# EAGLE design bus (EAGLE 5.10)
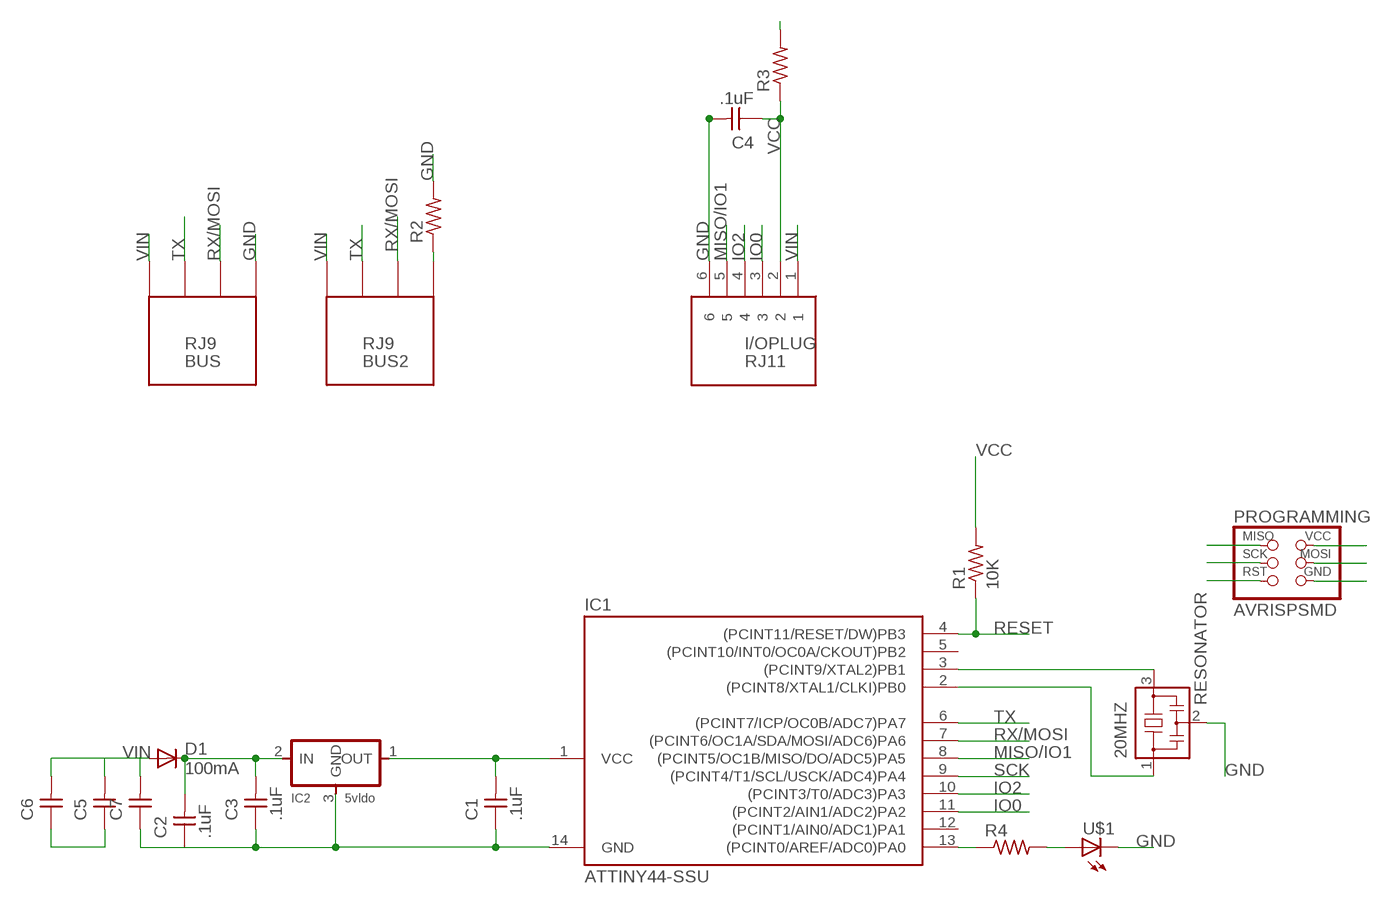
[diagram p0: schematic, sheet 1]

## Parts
20MHZ  RESONATOR  [EFOBM]
BUS  RJ9  [RJ9_SMD]
BUS2  RJ9  [RJ9_SMD]
C1  .1uF  UNPOLARIZED_CAPACITOR1206  [1206]
C2  .1uF  UNPOLARIZED_CAPACITOR1206  [1206]
C3  .1uF  UNPOLARIZED_CAPACITOR1206  [1206]
C4  .1uF  UNPOLARIZED_CAPACITOR1206  [1206]
C5  UNPOLARIZED_CAPACITOR1206  [1206]
C6  UNPOLARIZED_CAPACITOR1206  [1206]
C7  UNPOLARIZED_CAPACITOR1206  [1206]
D1  100mA  DIODESOD123  [SOD123]
I/OPLUG  RJ11  [RJ11_SMD]
IC1  ATTINY44-SSU  [SOIC14]
IC2  5vldo  REGULATORSOT23  [SOT23]
PROGRAMMING  AVRISPSMD  [2X03SMD]
R1  10K  RESISTOR1206  [1206]
R2  RESISTOR1206  [1206]
R3  RESISTOR1206  [1206]
R4  RESISTOR1206  [1206]
U$1  LED1206  [1206]

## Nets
GND: 20MHZ.2 BUS.4 C1.1 C2.1 C3.1 C4.2 C7.1 I/OPLUG.6 IC1.14(GND) IC2.3(GND) PROGRAMMING.6(GND) R2.2 U$1.2(C)
GND1: BUS2.4 C5.1 C6.1 R2.1
IO0: I/OPLUG.3 IC1.11((PCINT2/AIN1/ADC2)PA2)
IO2: I/OPLUG.4 IC1.10((PCINT3/T0/ADC3)PA3)
MISO/IO1: I/OPLUG.5 IC1.8((PCINT5/OC1B/MISO/DO/ADC5)PA5) PROGRAMMING.1(MISO)
N$1: 20MHZ.3 IC1.3((PCINT9/XTAL2)PB1)
N$2: 20MHZ.1 IC1.2((PCINT8/XTAL1/CLKI)PB0)
N$4: C4.1 I/OPLUG.2 R3.1
N$5: IC1.13((PCINT0/AREF/ADC0)PA0) R4.1
N$6: C2.2 C3.2 D1.CATHODE(C) IC2.2(IN)
N$7: R4.2 U$1.1(A)
RESET: IC1.4((PCINT11/RESET/DW)PB3) PROGRAMMING.5(RST) R1.1
RX/MOSI: BUS2.3 BUS.3 IC1.7((PCINT6/OC1A/SDA/MOSI/ADC6)PA6) PROGRAMMING.4(MOSI)
SCK: IC1.9((PCINT4/T1/SCL/USCK/ADC4)PA4) PROGRAMMING.3(SCK)
TX: BUS2.2 BUS.2 IC1.6((PCINT7/ICP/OC0B/ADC7)PA7)
VCC: C1.2 IC1.1(VCC) IC2.1(OUT) PROGRAMMING.2(VCC) R1.2 R3.2
VIN: BUS2.1 BUS.1 C5.2 C6.2 C7.2 D1.ANODE(A) I/OPLUG.1
Unconnected: IC1.5((PCINT10/INT0/OC0A/CKOUT)PB2) IC1.12((PCINT1/AIN0/ADC1)PA1)

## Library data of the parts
20MHZ = fab:RESONATOR
BUS BUS2 = nadya:RJ9
C1-C7 = ng:UNPOLARIZED_CAPACITOR: unpolarized_capacitor
D1 = ng:DIODE: DIODE
I/OPLUG = nadya:RJ11
IC1 = fab:ATTINY44
IC2 = fab:REGULATOR
PROGRAMMING = fab:AVRISP
R1-R4 = ng:RESISTOR
U$1 = ng:LED

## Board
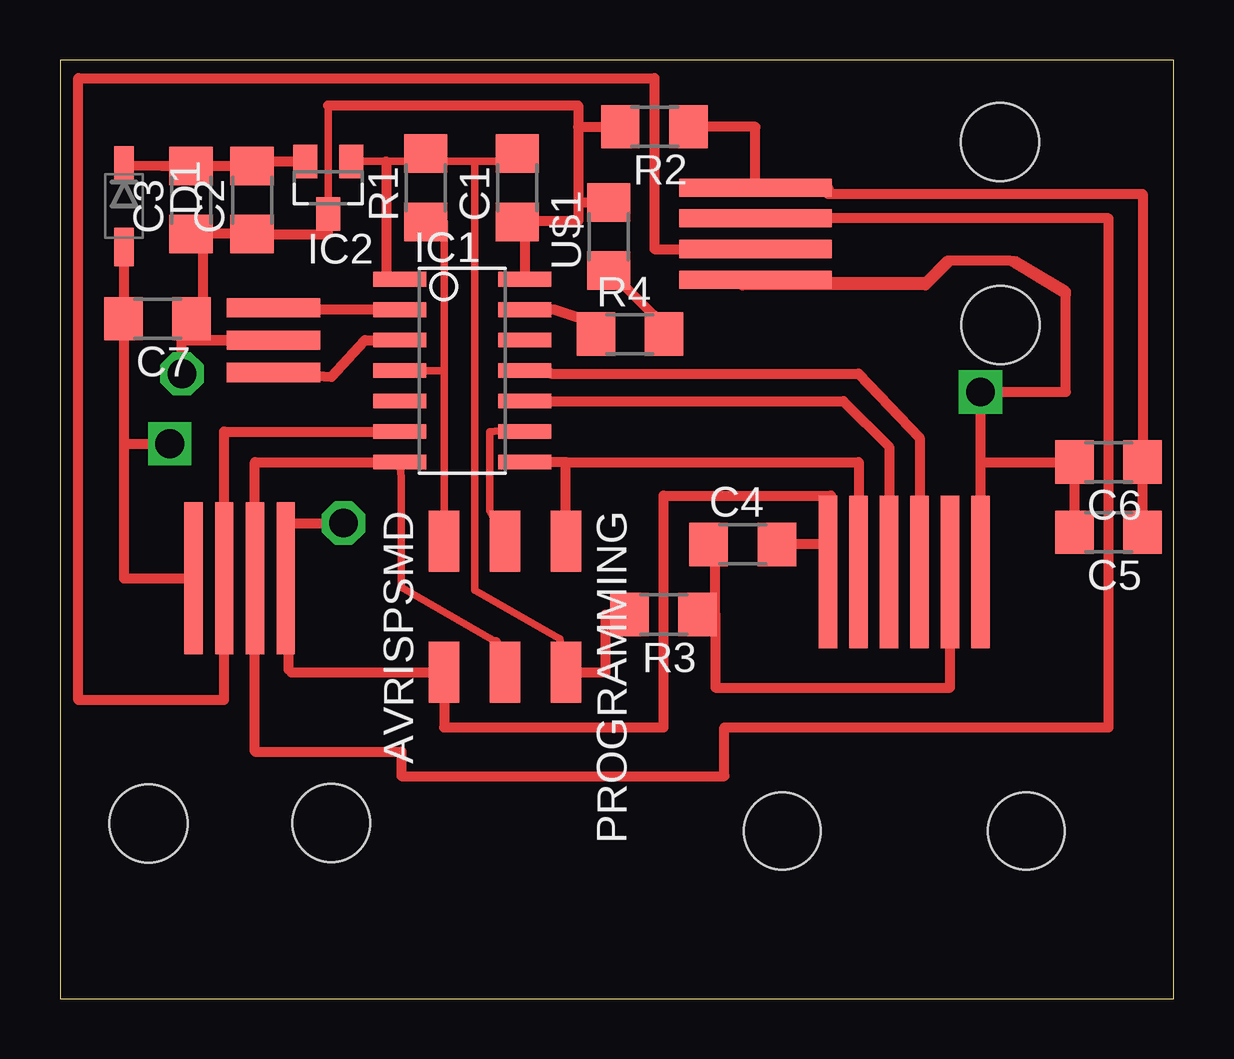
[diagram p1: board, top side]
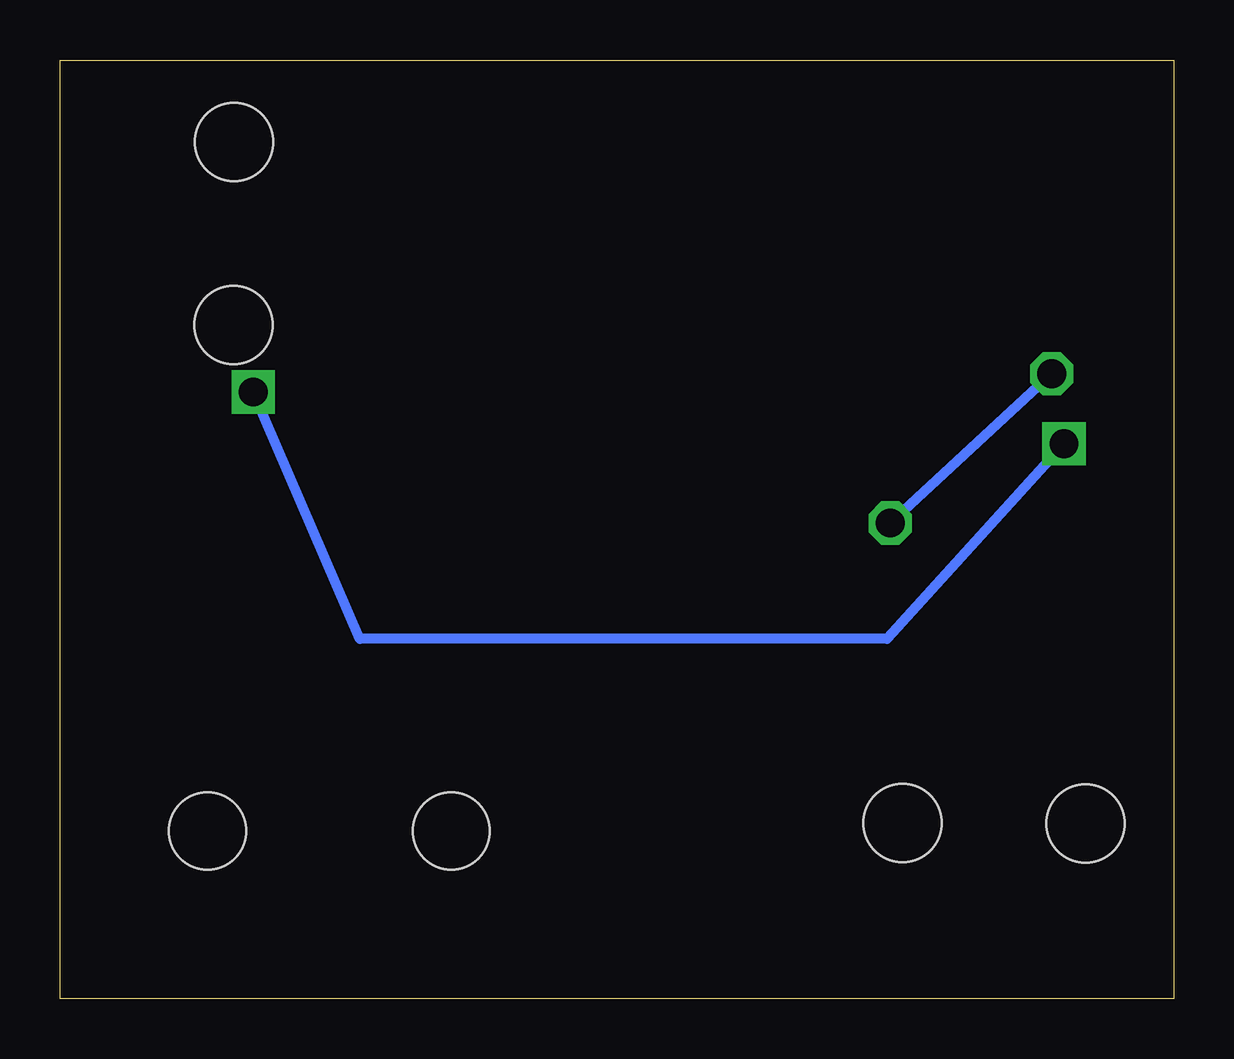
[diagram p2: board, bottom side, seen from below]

Size 46.41 x 39.11 mm. Coordinates in mm from the lower left corner, seen from the top.
Outline: 0,0 46.41,0 46.41,39.11 0,39.11 0,0
Copper layers (1*16): Top 0.035mm / dielectric 1.5mm / Bottom 0.035mm
Design rules "default": minimum track width 10mil, minimum drill 24mil, track to track 8mil, track to pad 8mil, pad to pad 8mil, via to via 8mil, smd to smd 8mil, copper to edge 40mil, drill to drill 8mil, minimum pad ring 10mil, minimum via ring 8mil, stop-mask expansion 4mil, vias tented up to drill 0mil, thermal gap 10mil

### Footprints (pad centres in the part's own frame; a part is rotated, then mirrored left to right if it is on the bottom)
EFOBM = smd 0.8 x 3.9: 1 -1.35,0; 2 0,0; 3 1.35,0
RJ9_SMD = smd 0.76 x 6.35: 1 -1.93,3.16; 2 -0.65,3.16; 3 0.63,3.16; 4 1.91,3.16 | hole 3.25: -3.81,-7.05; 3.81,-7.03
1206 = smd 1.6 x 1.803: 1 -1.422,0; 2 1.422,0
SOD123 = smd 1.6 x 0.8: ANODE 1.7,0; CATHODE -1.7,0
RJ11_SMD = smd 0.762 x 6.35: 1 3.175,-3.175; 2 1.905,-3.175; 3 0.635,-3.175; 4 -0.635,-3.175; 5 -1.905,-3.175; 6 -3.175,-3.175 | hole 3.2: -5.08,-13.97; 5.08,-13.97
SOIC14 = smd 0.61 x 2.21: 1 -3.81,-2.603; 2 -2.54,-2.603; 3 -1.27,-2.603; 4 0,-2.603; 5 1.27,-2.603; 6 2.54,-2.603; 7 3.81,-2.603; 8 3.81,2.603; 9 2.54,2.603; 10 1.27,2.603; 11 0,2.603; 12 -1.27,2.603; 13 -2.54,2.603; 14 -3.81,2.603
SOT23 = smd 1 x 1.4: 1 -0.95,-1.1; 2 0.95,-1.1; 3 0,1.1
2X03SMD = smd 2.54 x 1.27: 1 -2.54,2.54; 2 2.92,2.54; 3 -2.54,0; 4 2.92,0; 5 -2.54,-2.54; 6 2.92,-2.54

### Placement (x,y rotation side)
20MHZ  8.89,27.43 270 top
BUS  7.49,14.35 0 top
BUS2  32.13,31.88 90 top
C1  19.05,33.78 90 top
C2  8,33.27 90 top
C3  5.46,33.27 90 top
C4  28.45,18.92 0 top
C5  43.69,19.43 180 top
C6  43.69,22.35 180 top
C7  4.06,28.32 180 top
D1  2.67,33.02 270 top
I/OPLUG  35.18,20.95 0 top
IC1  16.76,26.16 270 top
IC2  11.18,33.78 180 top
PROGRAMMING  18.54,16.51 270 top
R1  15.24,33.78 90 top
R2  24.77,36.32 180 top
R3  25.15,16 180 top
R4  23.75,27.69 0 top
U$1  22.86,31.75 90 top

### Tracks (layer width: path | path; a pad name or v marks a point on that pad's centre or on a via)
GND  (via drill 1.2 pad 1.78)
  Top 0.305: C1.1 19.37,32.36 | IC2.3 11.18,37.21
  Top 0.406: IC2.3 11.18,31.85 C2.1 7.62,31.88 5.97,31.88 5.97,31.24 | 19.37,32.36 IC1.14 | 9.45,18.92 9.53,17.25 9.53,13.72 9.65,13.59 PROGRAMMING.6 16,11.3 25.15,11.3 25.15,20.95 32.13,20.95 32.13,18.92 | 9.45,18.92 BUS.4 | 5.97,28.32 5.97,27.43 20MHZ.2 5.08,27.43 v5.08,26.03 | 5.97,28.32 5.97,31.24 | 11.18,37.21 21.59,37.21 21.59,36.32 | C1.1 19.05,32.39 21.59,32.39 21.59,33.17 | 21.59,36.32 R2.2 | 21.59,36.32 21.59,33.17 | v11.81,19.81 9.45,19.81 9.45,18.92 | 21.59,33.17 U$1.2 | C3.1 5.46,31.75 5.97,31.24 | I/OPLUG.6 32.13,17.91 32.13,18.92 | 32.13,18.92 C4.2 | 5.97,28.32 C7.1
  Bottom 0.406: v11.81,19.81 v5.08,26.03
GND1
  Top 0.406: R2.1 28.97,36.32 BUS2.4 32,33.79 32,33.53 45.11,33.53 C6.1 C5.1
IO0
  Top 0.406: IC1.11 20.32,26.16 20.45,26.03 33.27,26.03 35.81,23.37 I/OPLUG.3
IO2
  Top 0.406: IC1.10 32.64,24.89 34.54,22.99 I/OPLUG.4
MISO/IO1
  Top 0.406: 21.08,22.35 IC1.8 | PROGRAMMING.1 21.08,22.35 | 21.08,22.35 33.27,22.35 I/OPLUG.5
N$1
  Top 0.406: 8.51,25.91 20MHZ.3 11.3,25.91 12.7,27.43 IC1.3
N$2
  Top 0.406: IC1.2 8.51,28.7 20MHZ.1
N$4
  Top 0.406: R3.1 27.3,16 | 27.3,16 27.3,12.95 37.08,12.95 I/OPLUG.2 | 27.3,16 27.3,18.77 C4.1
N$5
  Top 0.406: R4.1 21.72,28.32 20.57,28.7 IC1.13
N$6
  Top 0.406: IC2.2 7.62,34.88 C2.2 C3.2 4.24,34.7 D1.CATHODE
N$7
  Top 0.406: U$1.1 25.27,27.94 R4.2
RESET
  Top 0.305: R1.1 16,32.36 16,26.16 | IC1.4 16,26.16 | 16,26.16 PROGRAMMING.5
RX/MOSI
  Top 0.305: 18.16,14.86 14.22,17.15 14.22,21.72 IC1.7
  Top 0.406: IC1.7 8.12,22.35 BUS.3 8.12,10.29 14.22,10.29 14.22,9.27 27.69,9.27 27.69,11.3 43.69,11.3 43.69,32.51 BUS2.3 | PROGRAMMING.4 18.16,13.97 18.16,14.86
SCK
  Top 0.305: PROGRAMMING.3 17.91,20.32 17.91,23.62 19.18,23.75 IC1.9
TX
  Top 0.406: IC1.6 6.84,23.62 BUS.2 6.84,12.45 0.76,12.45 0.76,38.35 24.77,38.35 24.77,31.23 BUS2.2
VCC
  Top 0.305: 21.34,13.72 PROGRAMMING.2 20.83,14.99 17.27,17.02 17.27,34.88 | 16,34.88 13.59,34.88 IC2.1 | 16,34.88 R1.2 | 17.27,34.88 18.8,34.88 C1.2 | 17.27,34.88 16,34.88
  Top 0.406: IC1.1 13.59,29.97 13.59,34.88 | PROGRAMMING.2 22.73,13.59 22.73,16 R3.2
VIN  (via drill 1.2 pad 1.78)
  Top 0.406: BUS.1 2.67,17.51 2.67,23.11 | 2.67,23.11 2.67,27.69 2.67,28.32 | 2.67,28.32 D1.ANODE | 37.08,30.73 36.96,30.73 36.07,29.84 28.31,29.84 BUS2.1 28.44,29.72 36.07,29.72 37.08,30.73 | 39.62,30.73 39.75,30.73 41.91,29.46 41.91,29.34 | 38.35,22.35 I/OPLUG.1 | 39.62,30.73 37.08,30.73 | 41.91,29.34 39.62,30.73 | 41.91,29.34 41.91,25.27 v38.35,25.27 38.35,22.35 | 2.67,23.11 v4.57,23.11 | 38.35,22.35 C6.2 C5.2 | 2.67,28.32 C7.2
  Bottom 0.406: v4.57,23.11 11.94,14.99 33.91,14.99 v38.35,25.27 38.48,25.27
